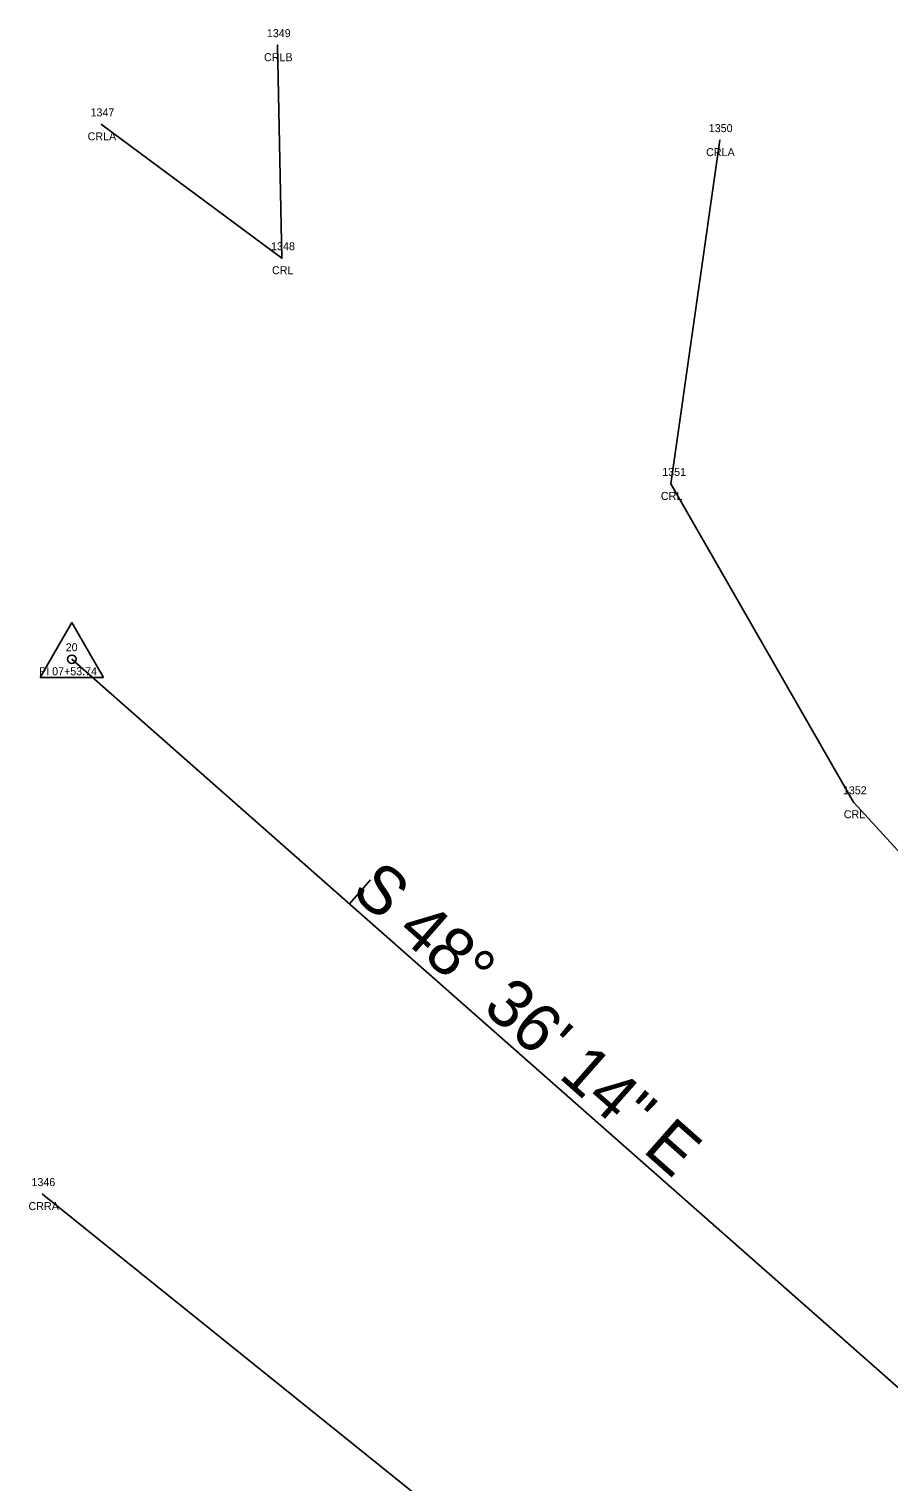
# Model space of a CAD drawing. Extents: x 2432632 to 2433497, y 684847 to 688233.
# Drawn here: x 2432921.4 to 2433028.9, y 686041.7 to 686223.3 of the extents above; entities that cross this region are included whole.
import ezdxf

# ---------------------------------------------------------------- set-up
doc = ezdxf.new("R2010")
doc.units = 0
for name, color, linetype in [('RD_EX_H2O', 7, 'Continuous'), ('RD_EX_H2O_txCode', 7, 'Continuous'), ('RD_HC_Cl', 7, 'Continuous'), ('RD_HC_Data', 7, 'Continuous'), ('RD_HC_Data_Tic', 7, 'Continuous'), ('RD_HC_txCode', 7, 'Continuous'), ('RD_SMD_Locator', 7, 'Continuous')]:
    doc.layers.add(name, color=color, linetype=linetype)

msp = doc.modelspace()

# ---------------------------------------------------------------- linework, layer by layer
at = {"layer": 'RD_EX_H2O'}
for points in [[(2432930.41, 686211.35), (2432952.98, 686194.62), (2432952.45, 686221.25)], [(2433007.74, 686209.38), (2433001.59, 686166.41), (2433024.46, 686126.62), (2433051.58, 686097.06), (2433120.95, 686072.12), (2433152.82, 686065.09), (2433205.51, 686026.38), (2433335.15, 685993.61)], [(2432923.04, 686077.65), (2433019.93, 685999.69), (2433090.75, 685956.18), (2433102.59, 685949.56), (2433131.31, 685944.06), (2433132.23, 685945.04), (2433164.1, 685935.07), (2433204.66, 685929.9), (2433314.75, 685896.03)]]:
    msp.add_lwpolyline(points, dxfattribs=at)
at = {"layer": 'RD_HC_Cl'}
msp.add_line((2432926.72, 686144.5), (2433035.76, 686048.38), dxfattribs=at)
at = {"layer": 'RD_HC_Data'}
for p, q in [((2432922.75, 686142.2), (2432926.72, 686149.08)), ((2432926.72, 686149.08), (2432930.69, 686142.2)), ((2432922.75, 686142.2), (2432930.69, 686142.2))]:
    msp.add_line(p, q, dxfattribs=at)
msp.add_circle((2432926.72, 686144.5), 0.529, dxfattribs=at)
at = {"layer": 'RD_HC_Data_Tic'}
msp.add_line((2432961.43, 686113.91), (2432964.07, 686116.91), dxfattribs=at)
at = {"layer": 'RD_SMD_Locator'}
for centre in [(2432952.45, 686221.25), (2432930.41, 686211.35), (2433007.74, 686209.38), (2432952.98, 686194.62), (2433001.59, 686166.41), (2432926.72, 686144.5), (2433024.46, 686126.62), (2432923.04, 686077.65)]:
    msp.add_circle(centre, 0.001, dxfattribs=at)

# ---------------------------------------------------------------- texts
at = {"layer": 'RD_EX_H2O_txCode'}
for s, p in [('1349', (2432951.1, 686222.25)), ('CRLB', (2432950.75, 686219.25)), ('1347', (2432929.06, 686212.35)), ('1350', (2433006.35, 686210.38)), ('CRLA', (2432928.69, 686209.35)), ('CRLA', (2433006.02, 686207.38)), ('1348', (2432951.63, 686195.62)), ('CRL', (2432951.75, 686192.62)), ('1351', (2433000.53, 686167.41)), ('CRL', (2433000.36, 686164.41)), ('1352', (2433023.12, 686127.62)), ('CRL', (2433023.23, 686124.62)), ('1346', (2432921.67, 686078.65)), ('CRRA', (2432921.3, 686075.65))]:
    msp.add_text(s, height=1, dxfattribs=at).set_placement(p)
at = {"layer": 'RD_HC_Data'}
msp.add_text('S 48%%d 36\' 14" E', height=6, rotation=318.6038, dxfattribs=at).set_placement((2432961.47, 686115.2))
at = {"layer": 'RD_HC_txCode'}
for s, p in [('20', (2432925.95, 686145.5)), ('PI 07+53.74', (2432922.62, 686142.5))]:
    msp.add_text(s, height=1, dxfattribs=at).set_placement(p)

doc.saveas('drawing.dxf')
